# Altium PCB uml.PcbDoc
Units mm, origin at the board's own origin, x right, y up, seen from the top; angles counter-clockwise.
Board outline 71 x 50 mm, 2 copper layers (Top Layer, Bottom Layer); 99 components, 45 nets, 273 pads, 61 vias.
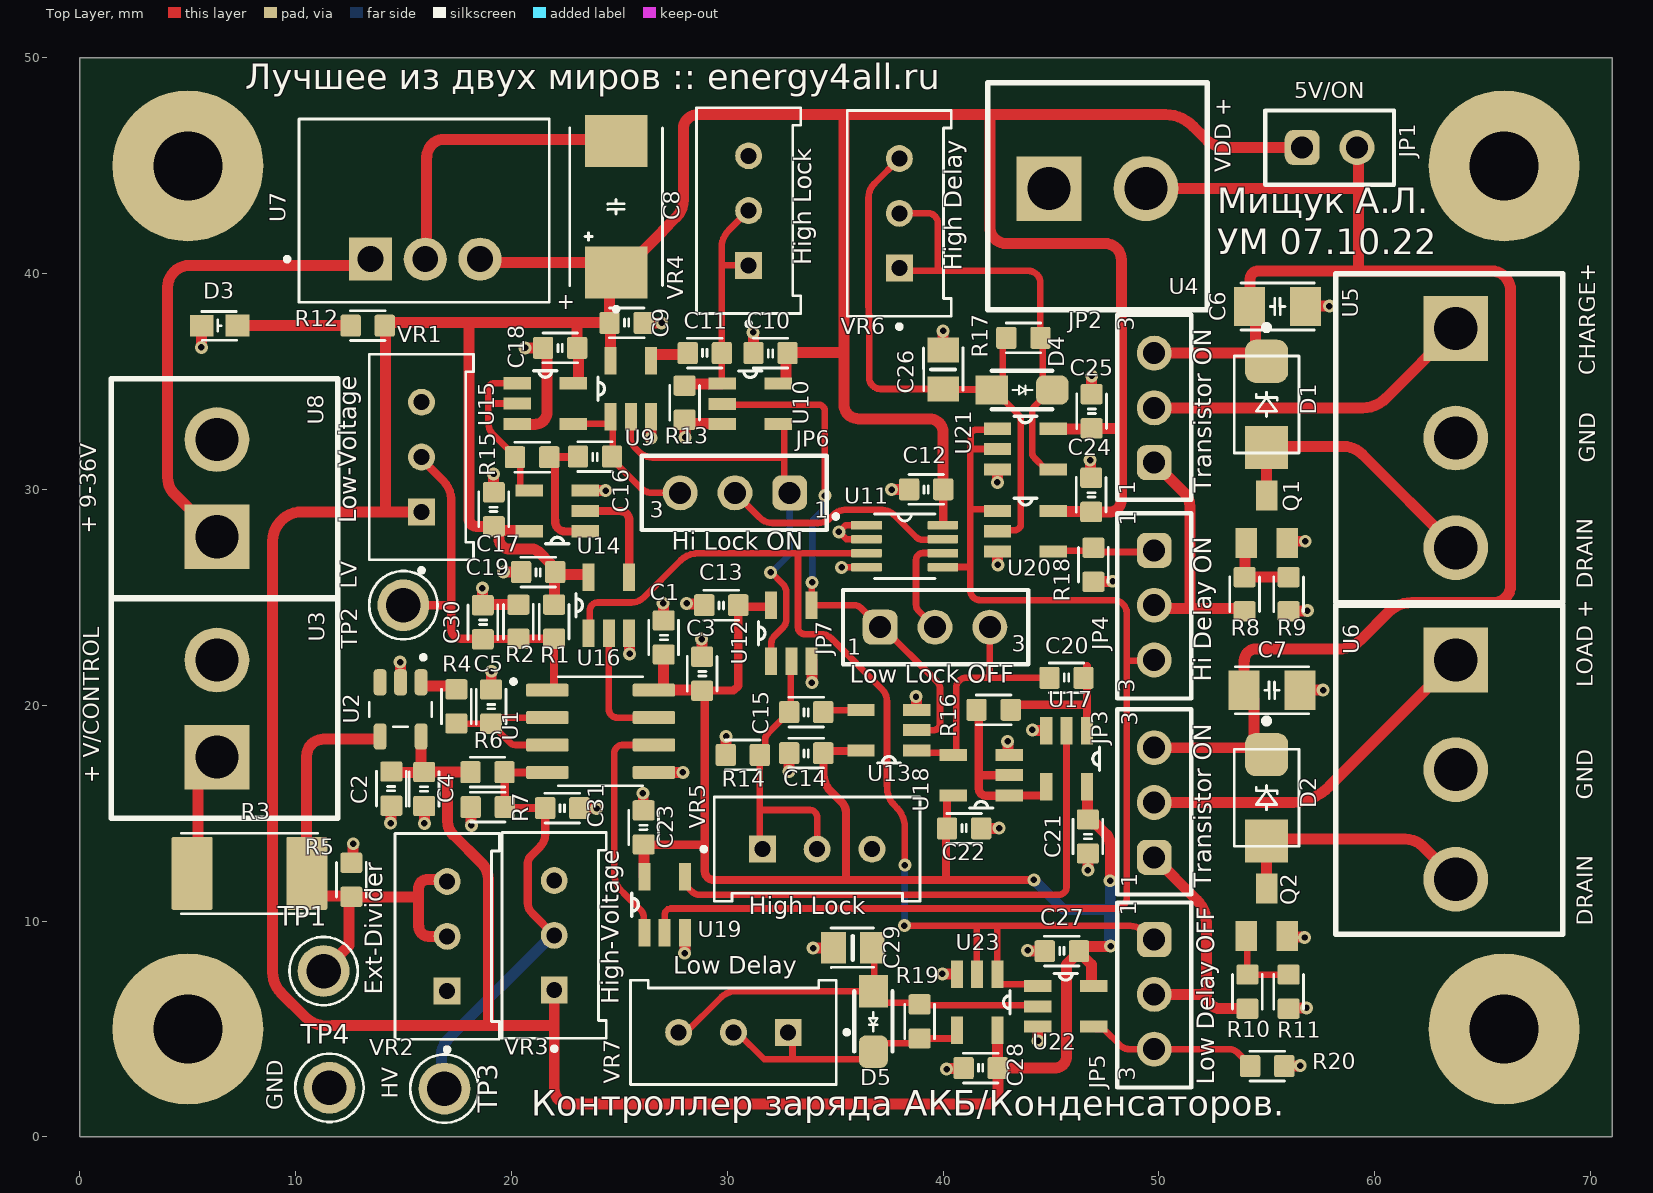
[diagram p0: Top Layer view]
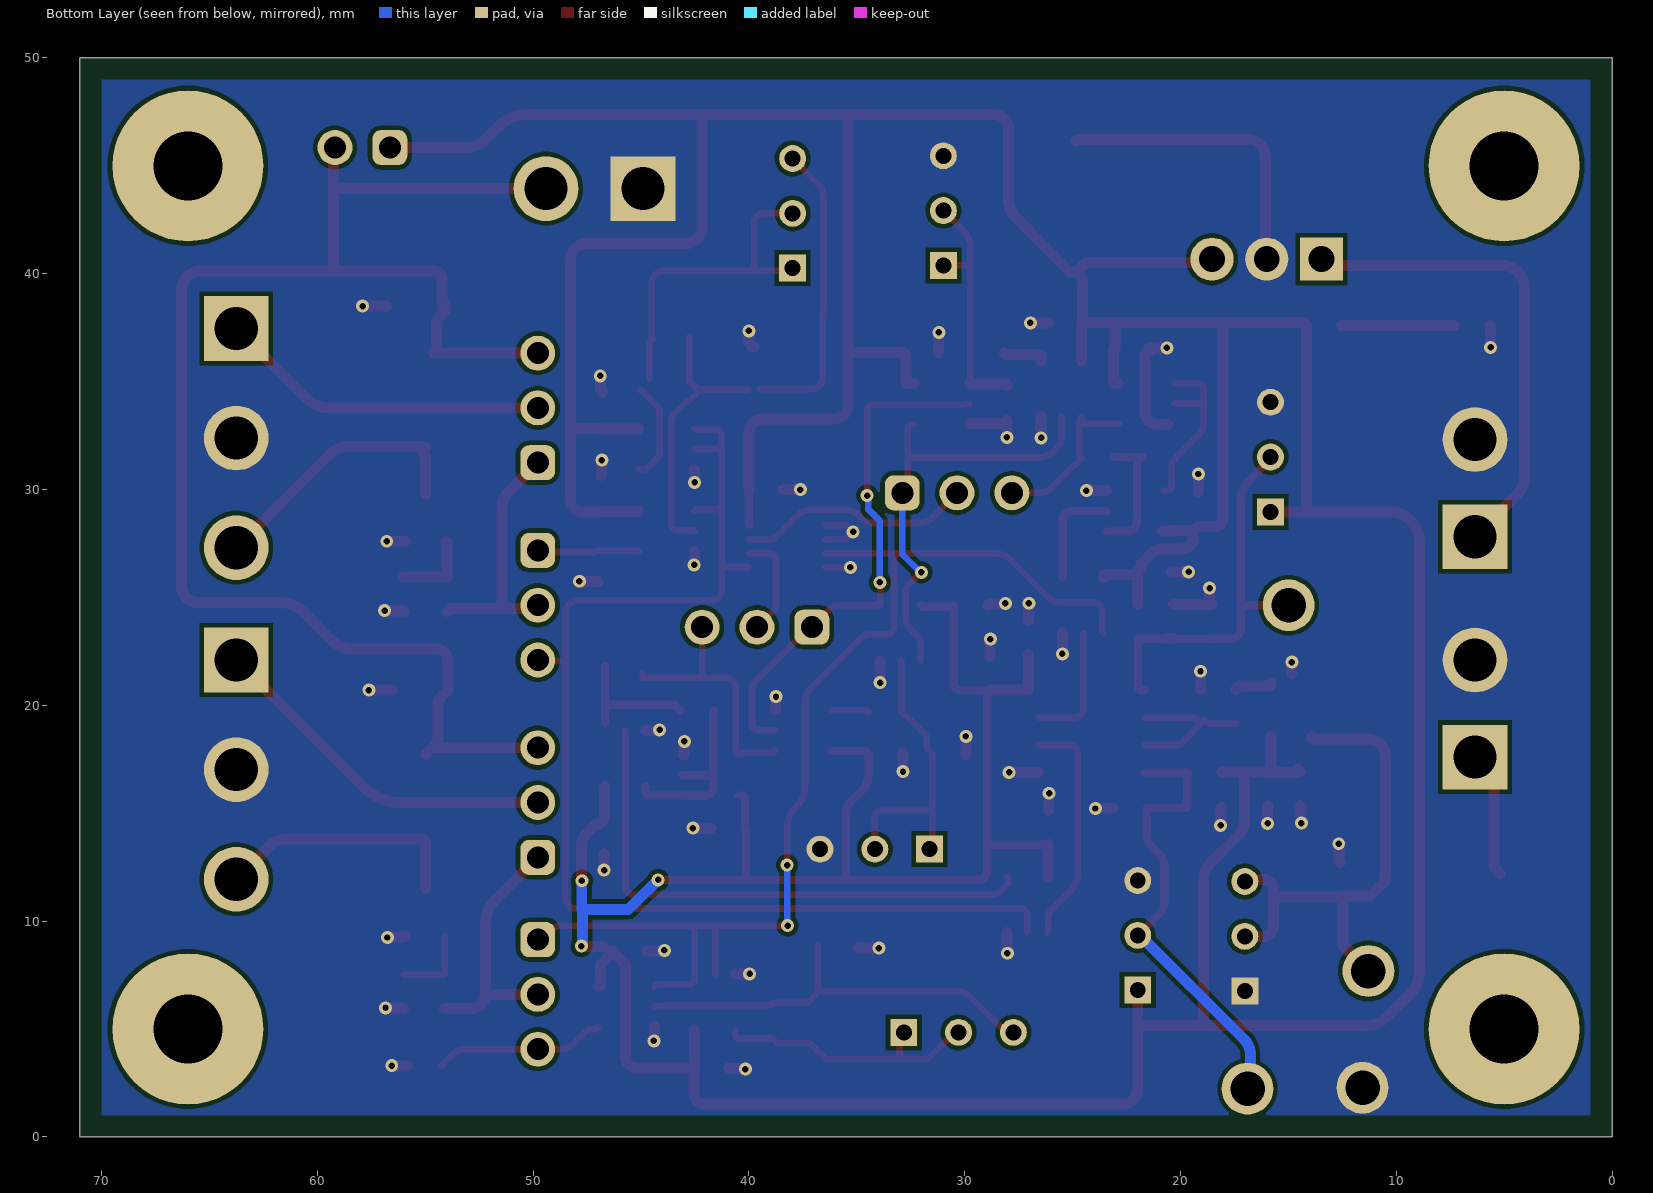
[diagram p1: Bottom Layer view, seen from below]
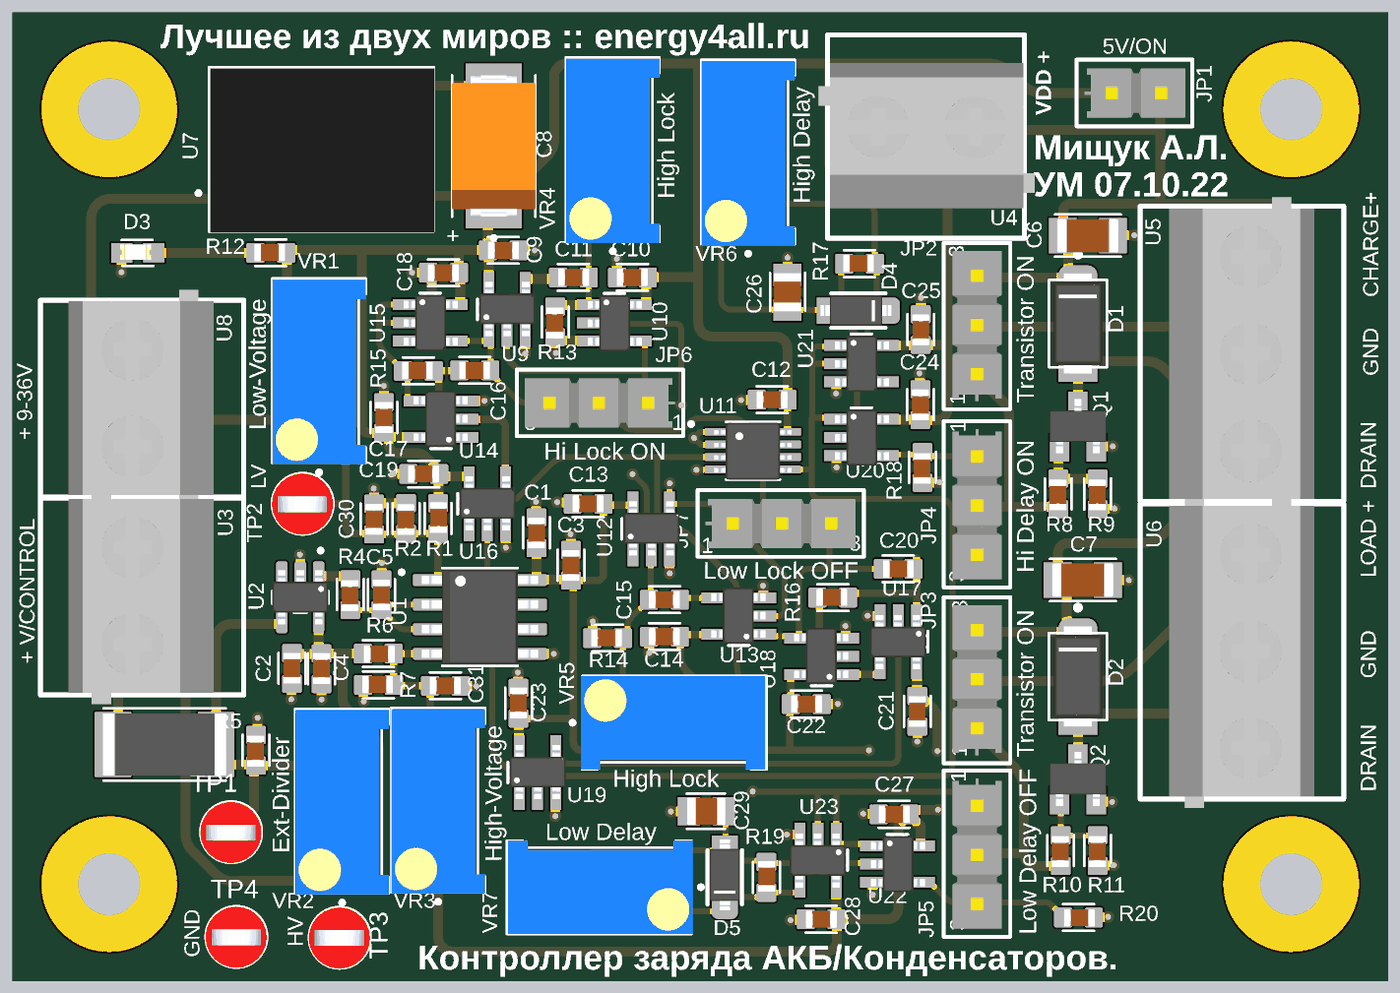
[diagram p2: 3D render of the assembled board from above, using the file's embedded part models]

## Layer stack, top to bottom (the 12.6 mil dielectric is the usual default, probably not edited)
Top Solder: solder mask 0.0102, Solder Resist, Dk 3.5
Top Layer: signal copper 0.0356
Dielectric 1: dielectric 0.32, FR-4, Dk 4.8
Bottom Layer: signal copper 0.0356
Bottom Solder: solder mask 0.0102, Solder Resist, Dk 3.5

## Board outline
0,0 71,0 71,50 0,50

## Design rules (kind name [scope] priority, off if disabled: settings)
Clearance [All] p1: gap=0.2 ignorepadtopadclearanceinfootprint=FALSE except(0: Arc-Hole Track-Hole SMDPad-Hole THPad-Hole Via-Hole Fill-Hole Poly-Hole Region-Hole Text-Hole)
HoleSize [All] p1: absolutevalues=TRUE maxlimit=5.08 minlimit=0.025 maxpercent=80.000 minpercent=20.000
MinimumSolderMaskSliver [All] p1 off: minsoldermaskwidth=0.254
PasteMaskExpansion [All] p1 off: expansion=0
PolygonConnect [All] p1: connectstyle=Direct reliefconductorwidth=0.254 reliefentries=4 polygonreliefangle="90 Angle" airgapwidth=0.254
RoomDefinition lockgen [InComponentClass('lockgen')] p1: confinementstyle=ConfineOut formatcopy=TRUE lockcomponents=FALSE outline 44.755,-5.766 49.301,-5.766 49.301,-2.311 44.755,-2.311
RoomDefinition uDelay [InComponentClass('uDelay')] p2: confinementstyle=ConfineOut formatcopy=TRUE lockcomponents=FALSE outline 50.14,-5.715 54.813,-5.715 54.813,-2.21 50.14,-2.21
RoomDefinition lock [InComponentClass('lock')] p3: confinementstyle=ConfineOut formatcopy=TRUE lockcomponents=FALSE outline 39.497,-5.766 44.12,-5.766 44.12,-2.337 39.497,-2.337
RoomDefinition uSupply [InComponentClass('uSupply')] p4: confinementstyle=ConfineOut formatcopy=TRUE lockcomponents=FALSE outline 33.731,-5.664 38.862,-5.664 38.862,-2.21 33.731,-2.21
RoomDefinition uPower [InComponentClass('uPower')] p5: confinementstyle=ConfineOut formatcopy=TRUE lockcomponents=FALSE outline 27.788,-5.613 32.944,-5.613 32.944,-2.21 27.788,-2.21
RoomDefinition uVoltage [InComponentClass('uVoltage')] p6: confinementstyle=ConfineOut formatcopy=TRUE lockcomponents=FALSE outline 21.895,-5.537 26.899,-5.537 26.899,-2.235 21.895,-2.235
RoutingVias [All] p1: holewidth=0.711 width=1.27 viastyle="Through Hole" minholewidth=0.711 minwidth=1.27 maxholewidth=0.711 maxwidth=1.27
SilkToSilkClearance [All] p1 off: silktosilkclearance=0.127
SilkToSolderMaskClearance [IsPad] p1 off: minsilkscreentomaskgap=0.254 clearancetoexposedcopper=TRUE
SolderMaskExpansion [All] p1 off: expansion=0.102 istentingtop=FALSE
Width [All] p1: maxlimit=1.27 minlimit=0.254 preferedwidth=0.508
25 further rules are at their usual default settings.

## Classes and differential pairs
component class uDelay: C24 C25 C26 C27 C28 C29 D4 D5 JP4 JP5 R17 R18 R19 R20 U20 U21 U22 U23 VR6 VR7
component class lock: C9 C10 C11 C12 C13 C14 C15 JP6 JP7 R13 R14 U9 U10 U11 U12 U13 VR4 VR5
component class lockgen: C16 C17 C18 C19 C20 C21 C22 C23 R15 R16 U14 U15 U16 U17 U18 U19
component class uSupply: C8 D3 R12 U7 U8
component class uPower: C6 C7 D1 D2 JP1 JP2 JP3 Q1 Q2 R8 R9 R10 R11 U4 U5 U6
component class uVoltage: C1 C2 C3 C4 C5 C30 C31 R1 R2 R3 R4 R5 R6 R7 TP1 TP2 TP3 TP4 U1 U2 U3 VR1 VR2 VR3

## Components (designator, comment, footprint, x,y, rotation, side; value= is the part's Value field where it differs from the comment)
C1 "2.2uF" CAP_0603 27.051,23.142 r90 top
C2 "2.2uF" CAP_0603 14.431,16.139 r270 top
C3 "0.1uF" CAP_0603 28.829,21.463 r90 top
C4 "0.1uF" CAP_0603 15.954,16.12 r270 top
C5 "5pF" CAP_0603 19.05,19.939 r90 top
C6 "0.1uF" CAP_1206 55.503,38.481 r180 top
C7 "0.1uF" CAP_1206 55.245,20.701 r180 top
C8 "100uF" CAP_TYPE_D 24.845,43.107 r90 top
C9 "0.1uF" CAP_0603 25.335,37.721 r180 top
C10 "0.1uF" CAP_0603 32.004,36.322 r0 top
C11 "10nF" CAP_0603 28.956,36.322 r180 top
C12 "0.1uF" CAP_0603 39.215,30.01 r0 top
C13 "0.1uF" CAP_0603 29.718,24.638 r0 top
C14 "0.1uF" CAP_0603 33.655,17.78 r0 top
C15 "10nF" CAP_0603 33.655,19.685 r0 top
C16 "10nF" CAP_0603 23.866,31.526 r0 top
C17 "0.1uF" CAP_0603 19.177,29.083 r270 top
C18 "0.1uF" CAP_0603 22.253,36.565 r0 top
C19 "0.1uF" CAP_0603 21.235,26.175 r0 top
C20 "10nF" CAP_0603 45.716,21.274 r180 top
C21 "0.1uF" CAP_0603 46.705,13.923 r90 top
C22 "0.1uF" CAP_0603 40.975,14.295 r180 top
C23 "0.1uF" CAP_0603 26.123,14.341 r270 top
C24 "0.1uF" CAP_0603 46.863,29.754 r90 top
C25 "0.1uF" CAP_0603 46.879,33.628 r90 top
C26 "10nF" CAP_0805 40.005,35.56 r270 top
C27 "0.1uF" CAP_0603 45.503,8.605 r180 top
C28 "0.1uF" CAP_0603 41.741,3.19 r180 top
C29 "10nF" CAP_0805 35.814,8.763 r0 top
C30 "10nF" CAP_0603 18.669,23.848 r90 top
C31 "10nF" CAP_0603 22.352,15.24 r0 top
D1 "MBRA340" MBRA340 54.991,33.691 r270 top
D2 "MBRA340" MBRA340 54.991,15.466 r270 top
D3 "LED/GREEN" LED_0603 6.496,37.592 r0 top
D4 "BAT46WJ" BAT46WJ 43.661,34.611 r0 top
D5 "BAT46WJ" BAT46WJ 36.766,5.351 r270 top
JP1 "5V OR EXT" TSW-102-07-F-S 57.912,45.847 r0 top
JP2 "logical/open drain" TSW-103-07-F-S 49.784,33.782 r90 top
JP3 "logical/open drain" TSW-103-07-F-S 49.784,15.494 r90 top
JP4 "Charge Delay ON/OFF" TSW-103-07-F-S 49.784,24.638 r270 top
JP5 "Load Delay ON/OFF" TSW-103-07-F-S 49.784,6.604 r270 top
JP6 "TSW-103-07-F-S" TSW-103-07-F-S 30.353,29.845 r180 top
JP7 "TSW-103-07-F-S" TSW-103-07-F-S 39.624,23.622 r0 top
Q1 "2N7002" 2N7002 54.991,28.618 r0 top
Q2 "2N7002" 2N7002 54.991,10.414 r0 top
R1 "1K 1%" RESC1608X50N 21.971,23.876 r270 top
R2 "500R 1%" RESC1608X50N 20.32,23.876 r90 top
R3 "499K" RES_2512 7.855,12.21 r0 top
R4 "680 1%" RESC1608X50N 17.442,19.95 r90 top
R5 "DNP" RESC1608X50N 12.575,11.914 r90 top
R6 "500R 1%" RESC1608X50N 18.887,16.9 r180 top
R7 "1K 1%" RESC1608X50N 18.897,15.285 r0 top
R8 "10R" RESC1608X50N 53.975,25.146 r90 top
R9 "10K" RESC1608X50N 56.007,25.146 r90 top
R10 "10R" RESC1608X50N 54.102,6.731 r90 top
R11 "10K" RESC1608X50N 56.007,6.731 r90 top
R12 "10K" RESC1608X50N 13.335,37.592 r0 top
R13 "DNP" RESC1608X50N 28.02,34.024 r90 top
R14 "DNP" RESC1608X50N 30.717,17.701 r0 top
R15 "5K" RESC1608X50N 20.955,31.496 r0 top
R16 "5K" RESC1608X50N 42.341,19.793 r0 top
R17 "DNP" RESC1608X50N 43.721,37.029 r0 top
R18 "100K" RESC1608X50N 46.966,26.512 r90 top
R19 "DNP" RESC1608X50N 38.914,5.351 r270 top
R20 "100K" RESC1608X50N 55.02,3.278 r180 top
TP1 "TP_RED" TP_RED 11.293,7.685 r0 top
TP2 "TP_RED" TP_RED 14.986,24.638 r0 top
TP3 "TP_RED" TP_RED 16.893,2.234 r0 top
TP4 "TP_RED" TP_RED 11.562,2.277 r0 top
U1 "TLV3502AID" TLV3502AID 24.13,18.796 r0 top
U2 "BUF602IDBVT" BUF602IDBVT 14.859,19.812 r270 top
U3 "DG129-5.0-02P" DG129-5.0-02P 6.35,19.848 r90 top
U4 "External Supply" DG129-5.0-02P 47.153,43.942 r0 top
U5 "DG129-5.0-03P" DG129-5.0-03P 63.754,32.385 r270 top
U6 "DG129-5.0-03P" DG129-5.0-03P 63.754,17.018 r270 top
U7 "R-78E5.0-1.0" R-78E5.0-1.0 16.002,42.926 r0 top
U8 "DG129-5.0-02P" DG129-5.0-02P 6.35,30.063 r90 top
U9 "SN74LVC1G00DBVT" SOT23-5 25.527,34.671 r90 top
U10 "SN74LVC1G00DBVT" SOT23-5 31.06,33.972 r0 top
U11 "SN74LVC1G74DCTR" SN74LVC1G74DCTR 38.219,27.376 r0 top
U12 "SN74LVC1G00DBVT" SOT23-5 32.969,23.343 r90 top
U13 "SN74LVC1G00DBVT" SOT23-5 37.49,18.847 r180 top
U14 "SN74LVC1G02DBVT" SOT23-5 22.123,29.007 r180 top
U15 "SN74LVC1G02DBVT" SOT23-5 21.565,33.985 r0 top
U16 "SN74LVC1G00DBVT" SOT23-5 24.511,24.638 r90 top
U17 "SN74LVC1G02DBVT" SOT23-5 45.72,17.526 r270 top
U18 "SN74LVC1G02DBVT" SOT23-5 41.765,16.766 r180 top
U19 "SN74LVC1G00DBVT" SOT23-5 27.098,10.763 r90 top
U20 "SN74LVC1G08DBVT" SOT23-5 43.815,28.067 r0 top
U21 "SN74LVC1G08DBVT" SOT23-5 43.815,31.877 r0 top
U22 "SN74LVC1G08DBVT" SOT23-5 45.68,6.047 r0 top
U23 "SN74LVC1G08DBVT" SOT23-5 41.577,6.245 r270 top
VR1 "5K" TRIM_3296W-1-250 15.829,31.506 r90 top
VR2 "10K" TRIM_3296W-1-250 17.018,9.296 r90 top
VR3 "5K" TRIM_3296W-1-250 21.979,9.339 r90 top
VR4 "5K" TRIM_3296W-1-250 30.988,42.926 r90 top
VR5 "5K" TRIM_3296W-1-250 34.163,13.335 r0 top
VR6 "3296W-1-250" TRIM_3296W-1-250 37.973,42.799 r90 top
VR7 "3296W-1-250" TRIM_3296W-1-250 30.283,4.845 r180 top

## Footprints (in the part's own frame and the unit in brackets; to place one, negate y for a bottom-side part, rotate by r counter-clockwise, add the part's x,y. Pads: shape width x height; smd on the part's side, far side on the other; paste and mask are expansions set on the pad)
2N7002 [mm]
  rect 1x1.4 smd: 1(-0.95,-1.1) 2(0.95,-1.1) 3(0,1.1)
  body extent -1.46,-1.37 1.47,1.43, height 1.24
BAT46WJ [mm]
  rect 1.5x1.35 smd: A(-1.4,0)
  rrect50% 1.5x1.35 smd: C(1.4,0)
  silkscreen extent -1.4,-0.89 1.4,0.89, body extent -1.95,-0.77 1.7,0.78, height 1.45
BUF602IDBVT [mm]
  rrect50% 1.21x0.59 smd: 1(-1.255,0.95) 2(-1.255,0) 3(-1.255,-0.95) 4(1.255,-0.95) 5(1.255,0.95)
  silkscreen extent -2.51,-1.45 0.8,1.45, body extent -1.4,-1.45 1.4,1.45, height 1.45
CAP_0603 [mm]
  rrect20% 0.94x1.02 smd: 1(-0.79,0) 2(0.79,0)
  silkscreen extent -0.8,-0.69 0.8,0.69, body extent -0.81,-0.45 0.79,0.45, height 0.81
CAP_0805 [mm]
  rect 1.15x1.45 smd: 1(-0.9,0) 2(0.9,0)
  silkscreen extent -1.01,-0.91 0.97,0.92, body extent -1,-0.72 1,0.72, height 1.26
CAP_1206 [mm]
  rect 1.44x1.82 smd: 1(-1.295,0) 2(1.295,0)
  silkscreen extent -1.7,-1.09 1.7,1.09, body extent -1.6,-0.89 1.6,0.89, height 1.56
CAP_TYPE_D [mm]
  rect 2.4x2.9 smd: 1(-3.05,0) 2(3.05,0)
  silkscreen extent -4.85,-2.15 3.65,2.15, body extent -3.65,-2.15 3.65,2.15, height 3.1
DG129-5.0-02P [mm]
  rect 3x3 hole 2: 1(-2.25,0)
  round 3 hole 2: 2(2.25,0)
  silkscreen extent -5.08,-5.6 5.08,4.9, body extent -5.55,-4.05 5.61,3.45, height 10.08
DG129-5.0-03P [mm]
  rect 3x3 hole 2: 1(-5.08,0)
  round 3 hole 2: 2(0,0) 3(5.08,0)
  silkscreen extent -7.62,-5.55 7.62,4.95, body extent -8.08,-4.05 8.08,3.45, height 10.08
LED_0603 [mm]
  rect 1.1x1 smd: 1(-0.85,0) 2(0.808,0.009)
  silkscreen extent -0.86,-0.67 0.77,0.66, body extent -0.92,-0.37 0.68,0.43, height 0.55
MBRA340 [mm]
  rect 2x2 smd: A(1.75,0)
  rrect50% 2x2 smd: C(-2.25,0)
  silkscreen extent -3.94,-1.5 2,1.5, body extent -2.86,-1.3 2.35,1.3, height 2.14
R-78E5.0-1.0 [mm]
  rect 2x2 hole 1.2: 1(-2.54,-2.25)
  round 2 hole 1.2: 2(0,-2.25) 3(2.54,-2.25)
  silkscreen extent -6.5,-4.25 5.75,4.25, body extent -5.8,-4.31 5.8,4.19, height 10.41
RES_2512 [mm]
  rrect7% 1.9x3.37 smd: 1(-2.66,0) 2(2.66,0)
  silkscreen extent -3.15,-1.87 3.15,1.87, body extent -3.17,-1.6 3.18,1.6, height 0.65
RESC1608X50N [mm]
  rrect20% 0.94x1.02 smd: 1(-0.79,0) 2(0.79,0)
  silkscreen extent -0.8,-0.69 0.8,0.69, body extent -0.85,-0.43 0.75,0.47, height 0.79
SN74LVC1G74DCTR [mm]
  rect 1.42x0.4 smd: 1(-1.77,0.975)
  rrect25% 1.42x0.4 smd: 2(-1.77,0.325) 3(-1.77,-0.325) 4(-1.77,-0.975) 5(1.77,-0.975) 6(1.77,-0.325) 7(1.77,0.325) 8(1.77,0.975)
  silkscreen extent -3.29,-1.5 1.4,1.5, body extent -2,-1.5 2,1.45, height 1.3
SOT23-5 [mil]
  rect 50x22 smd: 1(-51,37) 2(-51,0) 3(-51,-37) 4(51,-37) 5(51,37)
  silkscreen extent -21,48 21,60, body extent -54,-58 56,56, height 57
TLV3502AID [mm]
  rrect25% 1.97x0.6 smd: 1(-2.47,1.905) 2(-2.47,0.635) 3(-2.47,-0.635) 4(-2.47,-1.905) 5(2.47,-1.905) 6(2.47,-0.635) 7(2.47,0.635) 8(2.47,1.905)
  silkscreen extent -4.14,-2.52 1.95,2.52, body extent -3,-2.45 3,2.45, height 1.75
TP_RED [mm]
  round 2.4 hole 1.6: 1(0,0)
  silkscreen extent -1.59,-1.58 1.59,1.58, body extent -1.6,-1.61 1.57,1.57, height 8.13
TRIM_3296W-1-250 [mm]
  rect 1.248x1.248 hole 0.74: 1(-2.54,0)
  round 1.248 hole 0.74: 2(0,0) 3(2.54,0)
  silkscreen extent -5.35,-2.41 4.76,2.42, body extent -4.83,-2.42 4.7,2.42, height 11.55
TSW-102-07-F-S [mm]
  rrect50% 1.62x1.62 hole 1.02: 1(-1.27,0)
  round 1.62 hole 1.02: 2(1.27,0)
  silkscreen extent -2.99,-1.72 2.98,1.72, body extent -2.58,-1.28 2.62,1.26, height 8.38
TSW-103-07-F-S [mm]
  rrect50% 1.62x1.62 hole 1.02: 1(-2.54,0)
  round 1.62 hole 1.02: 2(0,0) 3(2.54,0)
  silkscreen extent -4.26,-1.72 4.32,1.72, body extent -3.85,-1.27 3.9,1.27, height 8.38

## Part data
C1 C2 C3 C4 C5 C9 C10 C11 C12 C13 C14 C15 C16 C17 C18 C19 C20 C21 C22 C23 C24 C25 C27 C28 C30 C31: library part CAP_0603
C6 C7: library part CAP_1206
C8: library part CAP_TYPE_D, Package=None
C26 C29: library part CAP_0805
D1 D2: "DIODE, SCHOTTKY, 3A, 40V, SMA", Package="DO-214 ON Semiconductor"
D3: library part LED_0603, "Blue 470nm LED Indication - Discrete 3.3V 0603 _1608 Metric_", Package="0603 Lite-On"
D4 D5: "Diode Schottky 100V 250mA (DC) Surface Mount SOD-323F", Package="SOD-323 NXP Semiconductors"
JP1: library part TSW-102-07-F-S
JP2 JP3 JP4 JP5: library part TSW-103-07-F-S
Q1 Q2: "N-Channel 60V 200mA _Tc_ 350mW _Tc_ Surface Mount SOT-23-3", Package="SOT-23-3 Vishay"
R1 R2 R4 R5 R6 R7 R8 R9 R10 R11 R12 R13 R14 R15 R16 R17 R18 R19 R20: library part RES_0603, "1% 0.1W", Package=None
R3: library part RES_2512, "2512 1% 1W", Package=None
TP1 TP2 TP3 TP4: "RF EMI Absorbing Sheet - Polyurethane Foam 24.000 (609.60mm) X 24.000 (609.60mm) X 0.252 (6.40mm)", Package="TO-66 Aeroflex"
U1: "4.5ns Rail-to-Rail Comparator", Package="SOIC-8 Texas Instruments"
U2: "1000MHz,Wide Bandwidth, High-Speed, Closed Loop Buffer 5-SOT-23 -45 to 85", Package="SOT-23-5 Texas Instruments"
U3 U8: "DG129-5.0-02P-14-00A(H)"
U4: library part DG129-5.0-02P, "DG129-5.0-02P-14-00A(H)"
U5 U6: "DG129-5.0-03P-14-00AH"
U7: "1A DC/DC-Converter SIP3", Package="SIP-3 Recom Power"
U9 U10 U12 U13 U16 U19: "NAND IC 1 canal SOT-23-5", Package="SOT-23 Texas Instruments"
U11: "Single Positive-Edge-Triggered D-Type Flip-Flop With Clear and Preset 8-SM8 -40 to 125", Package="SSOP-8 Texas Instruments"
U14 U15 U17 U18: "NOR IC 1 canal SOT-23-5", Package="SOT-23 Texas Instruments"
U20 U21 U22 U23: "AND IC 1 chanal SOT-23-5", Package="SOT-23 Texas Instruments"
VR1 VR2 VR3 VR4 VR5: library part 3296W-1-250, "25 Ohms 0.5W, 1/2W PC Pins Through Hole Trimmer Potentiometer Cermet 25 Turn Top Adjustment", Package="SOT-23-5 Bourns"
VR6 VR7: "25 Ohms 0.5W, 1/2W PC Pins Through Hole Trimmer Potentiometer Cermet 25 Turn Top Adjustment", Package="SOT-23-5 Bourns"

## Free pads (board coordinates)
  round 7 hole 3.2: 1(5,5) 2(5,45) 3(66,45) 4(66,5)

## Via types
v1: diameter 0.6, hole 0.3, Top Layer to Bottom Layer, tented both sides, 61 vias

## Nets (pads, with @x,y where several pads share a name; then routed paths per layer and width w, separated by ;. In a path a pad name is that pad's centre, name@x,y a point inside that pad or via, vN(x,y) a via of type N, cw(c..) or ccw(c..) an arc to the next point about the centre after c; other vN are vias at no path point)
+5V: C1.1 C2.1 C3.1 C4.1 C8.1 C9.2 C10.2 C12.2 C13.2 C14.2 C17.2 C18.2 C19.2 C21.2 C22.2 C23.2 C24.1 C25.1 C27.1 C28.1 JP1.1 R1.1 R6.2 R12.2 U1.8 U2.5 U7.3 U9.5 U10.5 U11.8 U12.5 U13.5 U14.5 U15.5 U16.5 U17.5 U18.5 U19.5 U20.5 U21.5 U22.5 U23.5 VR1.1 VR3.1 | length 308.6
  Top Layer w0.381: C23.2@26.211,13.515 26.232,13.536 28.956,13.536 ; C3.1 28.956,20.546 28.956,13.536 ; C3.1@28.838,20.682 30.285,20.682 30.508,20.905 C13.2@30.508,24.567 ; 29.365,11.907 35.494,11.907 ; 29.365,11.912 cw(c29.365,12.321) 28.956,12.321 28.956,13.536 ; C13.2 C13.2@30.508,24.567 ; U12.5 32.011,24.638 31.941,24.567 C13.2@30.508,24.567 ; C14.2@34.452,17.733 C14.2@34.462,17.743 ; C14.2@34.462,17.763 C14.2@34.462,17.743 ; 34.783,16.025 34.779,16.029 cw(c35.546,16.796) 34.705,16.112 cw(c35.546,16.796) 34.462,16.796 C14.2@34.462,17.743 ; 34.787,16.029 35.298,15.519 cw(c34.826,15.046) 35.494,15.046 35.494,11.907 ; U13.5@36.171,17.883 34.602,17.883 C14.2@34.462,17.743 ; U11.8 39.996,28.351 40.005,28.36 C12.2@40.005,29.972 ; U18.5 40.273,15.826 40.185,15.737 C22.2 40.132,14.243 40.132,11.907 ; v1(44.206,11.909) 44.204,11.907 40.132,11.907 ; 35.494,11.907 40.132,11.907
  Top Layer w0.508: 14.163,29.21 14.163,37.554 R12.2 14.272,37.739 18.034,37.739 ; C2.1 C2.1@14.562,17.06 ; C2.1@14.587,16.906 14.61,16.882 15.884,16.882 C4.1@15.937,16.936 ; C4.1@15.802,17.081 U2.5@15.802,18.55 ; VR1.1 10.289,28.966 ccw(c10.289,27.609) 8.932,27.609 8.932,7.619 8.932,7.617 ccw(c10.261,7.617) 9.323,6.675 10.43,5.568 ccw(c11.455,6.59) 11.705,5.165 cw(c11.793,4.664) 11.793,5.172 18.923,5.172 ; C4.1@15.964,16.918 17.037,16.918 ; R6.2 18.08,16.918 17.037,16.918 ; 18.375,28.293 C17.2 19.196,28.293 C17.2@19.397,28.092 ; 18.375,28.295 cw(c18.375,28.636) 18.034,28.636 18.034,37.739 ; U7.3 18.693,40.525 24.377,40.525 C8.1 ; 19.412,27.741 ccw(c19.91,27.741) 19.514,27.439 ccw(c19.91,27.741) 19.608,27.346 ccw(c19.91,27.741) 19.91,27.244 20.928,27.244 cw(c20.928,26.757) 21.235,27.135 cw(c20.928,26.757) 21.273,27.101 ; C17.2@19.412,28.092 20.447,28.092 20.472,28.067 U14.5 ; 21.271,27.1 21.809,26.562 21.809,26.391 C19.2 ; R1.1 21.998,24.693 21.998,26.148 C19.2 ; VR3.1 21.979,5.172 ; U15.5 23.087,34.925 23.112,34.95 C18.2@23.112,36.496 ; C18.2 23.03,36.578 23.03,37.739 ; U16.5 23.571,26.029 23.546,26.054 22.145,26.054 C19.2 ; U9.5 24.588,37.678 C9.2 ; C23.2@26.127,13.548 26.141,13.533 26.141,12.076 U19.5 ; U1.8@27.051,20.711 28.791,20.711 C3.1 ; U1.8@27.051,20.747 C1.1 ; 27.969,46.701 27.969,43.434 cw(c26.811,43.434) 27.63,42.616 27.002,41.988 27.002,41.964 25.095,40.057 C8.1 ; 27.969,46.821 cw(c28.627,46.701) 28.627,47.371 35.398,47.371 ; U10.5 32.683,34.912 32.709,34.937 C10.2@32.709,36.237 ; C10.2@32.813,36.341 35.398,36.341 ; C12.2@40.005,29.972 40.005,32.639 ccw(c39.37,32.639) 39.37,33.274 36.083,33.274 cw(c36.083,33.959) 35.398,33.959 35.398,36.341 ; C28.1@42.524,3.197 U23.5@42.524,4.943 ; 42.545,2.032 cw(c42.037,2.032) 42.037,1.524 22.679,1.524 cw(c22.679,2.224) 21.979,2.224 21.979,5.172 ; 42.554,2.032 C28.1@42.554,3.167 ; C28.1@42.554,3.189 45.167,3.189 ; U20.5 45.12,29.016 45.151,28.985 46.842,28.985 C24.1 47.119,28.956 47.698,28.956 ccw(c47.698,29.518) 48.26,29.518 48.26,32.826 ; U21.5 45.115,32.812 C25.1@46.854,32.812 ; 45.232,3.189 ccw(c45.167,3.738) 45.72,3.738 45.72,7.993 C27.1@46.293,8.565 ; C27.1 C27.1@46.293,8.565 ; U17.5@46.662,16.228 46.682,16.208 46.682,14.736 C21.2 46.921,14.497 47.08,14.497 47.531,14.046 cw(c47.001,13.516) 47.751,13.516 ; C27.1@46.732,8.822 47.748,8.822 v1(47.766,8.839) ; C25.1@46.868,32.826 48.26,32.826 ; U22.5 46.905,6.986 46.88,7.012 46.88,7.994 46.864,7.994 C27.1@46.293,8.565 ; v1(47.74,11.871) 47.753,11.884 47.753,13.516 ; 52.129,46.284 51.593,46.82 51.591,46.822 cw(c51.952,47.179) 51.587,46.826 ccw(c50.313,45.611) 50.313,47.371 50.311,47.371 42.164,47.371 ; 52.258,46.155 ccw(c53.156,47.311) 53.156,45.847 JP1.1 ; 17.037,16.918 17.037,14.618 ccw(c17.899,14.618) 17.298,14 18.633,12.664 cw(c17.934,11.965) 18.923,11.965 18.923,5.172 ; 18.034,37.739 23.03,37.739 ; 18.923,5.172 21.979,5.172 ; 23.03,37.739 24.527,37.739 C9.2 ; C9.2 24.545,39.758 C8.1 ; 35.398,36.341 35.398,47.371 ; 35.398,47.371 42.164,47.371 ; 42.164,47.371 42.164,42.168 ccw(c42.93,42.168) 42.93,41.402 47.503,41.402 cw(c47.503,40.645) 48.26,40.645 48.26,32.826
  Bottom Layer w0.508: v1(44.206,11.909) 44.694,11.42 ; 44.704,11.43 45.593,10.541 47.745,10.541 v1@47.745,11.866 ; 47.715,10.541 47.715,8.915 47.766,8.864 v1(47.766,8.839)
+12V: C6.2 C7.2 D1.C D2.C JP1.2 JP2.3 JP3.3 U4.2 | length 74.4
  Top Layer w0.508: U4.2@49.403,42.926 U4.2@50.038,43.561 ; U4.2 59.182,43.942 ; JP3.3 D2.C@54.673,18.034 ; JP2.3 D1.C@54.61,36.322 ; 53.95,22.079 C7.2 54.416,20.235 54.416,18.291 D2.C@54.673,18.034 ; 53.957,22.079 cw(c54.484,22.079) 54.484,22.606 58.293,22.606 ccw(c58.293,24.136) 59.375,23.054 ; C6.2@54.052,38.291 54.483,37.86 D1.C@54.483,36.449 ; C6.2@54.092,38.598 C6.2 ; C6.2@54.229,38.735 54.229,39.751 cw(c54.61,39.751) 54.61,40.132 59.242,40.132 ; D2.C D2.C@54.673,18.034 ; JP1.2 59.242,45.787 59.242,40.132 ; 59.399,23.077 60.638,24.316 cw(c61.722,23.232) 61.722,24.765 65.532,24.765 ccw(c65.532,25.527) 66.294,25.527 66.294,39.243 ccw(c65.405,39.243) 65.405,40.132 59.242,40.132
GND: C1.2 C2.2 C3.2 C4.2 C5.2 C6.1 C7.1 C8.2 C9.1 C10.1 C12.1 C13.1 C14.1 C17.1 C18.1 C19.1 C21.1 C22.1 C23.1 C24.2 C25.2 C26.1 C27.2 C28.2 C29.1 C30.2 C31.2 D3.1 Q1.2 Q2.2 R2.2 R5.2 R7.1 R9.1 R11.1 R13.1 R14.1 R18.1 R20.1 TP4.1 U1.5 U2.2 U3.2 U4.1 U5.2 U6.2 U7.2 U8.2 U9.3 U10.3 U11.1 U11.2 U11.4 U12.3 U13.3 U14.3 U15.3 U16.3 U17.3 U18.3 U19.3 U20.3 U21.3 U22.3 U23.3 VR1.3 VR2.1 VR3.3 VR4.3 VR5.3 | length 69
  Top Layer w0.305: v1(35.297,26.391) 35.302,26.396 36.444,26.396 U11.4 ; U11.2@36.433,27.685 36.425,27.692 35.523,27.692 v1(35.175,28.04) 35.487,28.352 36.434,28.352 U11.1@36.441,28.359
  Top Layer w0.508: v1(5.629,36.591) 5.638,36.599 5.638,37.584 D3.1 ; R5.2 12.648,12.777 12.648,13.568 v1(12.666,13.585) ; v1(14.397,14.543) 14.414,14.559 14.414,15.332 C2.2 ; v1(14.841,22.006) 14.859,21.989 U2.2@14.859,21.463 ; C4.2 15.957,15.327 15.957,14.529 v1(15.959,14.526) ; U7.2 16.066,40.74 16.066,45.438 ; 16.084,45.438 cw(c16.876,45.438) 16.876,46.23 24.772,46.23 C8.2 ; R7.1 18.123,15.269 18.123,14.449 v1(18.139,14.433) ; C30.2@18.544,24.666 R2.2 ; v1(18.649,25.435) 18.659,25.425 18.659,24.648 C30.2 ; C5.2 19.061,20.74 19.061,21.566 v1(19.072,21.578) ; v1(19.17,30.72) 19.173,30.717 19.173,29.877 C17.1 ; v1(19.625,26.181) 19.628,26.178 20.441,26.178 C19.1 ; U15.3@20.574,33.02 21.082,33.02 ccw(c21.082,33.58) 21.642,33.58 21.642,33.633 21.642,36.202 C18.1@21.371,36.473 ; v1(20.629,36.567) v1(20.629,36.567) 21.462,36.566 C18.1 ; C18.1@21.462,36.526 C18.1 ; C18.1 C18.1 ; C31.2 23.153,15.229 23.933,15.229 v1(23.944,15.218) ; U14.3 23.421,29.948 v1(24.362,29.95) v1(24.362,29.95) ; U16.3 25.461,23.332 25.461,22.39 v1(25.472,22.379) ; v1(26.088,15.925) 26.105,15.907 26.105,15.149 C23.1 ; C9.1 v1(26.958,37.721) ; v1(26.46,32.39) 26.463,32.394 26.463,33.372 U9.3 ; U1.5 v1(27.94,16.891) ; v1(27.027,24.73) 27.039,24.718 27.039,23.944 C1.2 ; v1(28.02,8.511) 28.029,8.52 28.029,9.459 U19.3 ; v1(28.041,32.421) 28.03,32.431 28.03,33.158 R13.1@28.074,33.201 ; R13.1@28.046,33.173 28.161,33.058 29.739,33.058 U10.3 ; v1(28.115,24.72) 28.133,24.703 28.863,24.703 C13.1 ; v1(28.81,23.064) 28.82,23.054 28.82,22.262 C3.2 ; R14.1 29.938,17.712 29.938,18.553 v1(29.949,18.564) ; v1(31.192,37.28) 31.203,37.269 31.203,36.333 C10.1 ; v1(32.858,16.929) 32.862,16.932 32.862,17.777 C14.1 ; U12.3 33.915,22.041 33.915,21.054 v1(33.921,21.048) ; v1(33.98,8.749) 33.988,8.756 34.891,8.756 C29.1@34.914,8.779 ; v1(37.613,29.991) 37.623,30.001 38.416,30.001 C12.1 ; v1(38.744,20.405) 38.761,20.387 38.761,19.811 U13.3 ; C26.1@39.751,36.601 39.825,36.601 40.005,36.781 v1(40.005,37.348) ; v1(39.969,7.557) 39.977,7.549 40.629,7.549 U23.3 ; v1(40.16,3.144) 40.178,3.161 40.922,3.161 C28.2 ; C22.1 41.77,14.3 42.589,14.3 v1(42.594,14.305) ; v1(42.51,30.331) 42.515,30.336 42.515,30.933 U21.3 ; U20.3 42.527,27.12 42.527,26.52 v1(42.534,26.512) ; v1(42.993,18.324) 43.01,18.307 43.01,17.731 43.036,17.706 U18.3 ; v1(43.913,8.639) 43.929,8.622 44.696,8.622 C27.2 ; v1(44.134,18.858) 44.152,18.841 44.761,18.841 U17.3 ; U22.3 44.395,5.096 44.395,4.463 v1(44.405,4.453) ; C21.1 46.706,13.132 46.706,12.359 v1(46.707,12.358) ; C25.2@46.78,34.527 46.884,34.631 46.884,35.266 v1(46.888,35.27) ; v1(46.813,31.366) 46.83,31.348 46.83,30.676 C24.2@46.863,30.643 ; R18.1 46.98,25.736 47.841,25.736 v1(47.855,25.75) ; R20.1 55.823,3.291 56.538,3.291 v1(56.551,3.305) ; Q2.2 55.997,9.258 56.738,9.258 v1(56.756,9.24) ; Q1.2@55.941,27.602 v1(56.783,27.602) ; R11.1 56.029,5.963 56.823,5.963 v1(56.84,5.981) ; R9.1 56.023,24.372 56.861,24.372 v1(56.878,24.389) ; C7.1 56.542,20.699 v1(57.611,20.699) ; C6.1 56.813,38.497 v1(57.899,38.497)
NetC5_1: C5.1 R4.1 U1.2 U1.3 | length 7.5
  Top Layer w0.305: R4.1 17.448,19.155 18.692,19.155 18.697,19.15 18.697,19.146 18.875,19.324 C5.1 ; U1.3 20.193,18.161 cw(c20.193,18.535) 19.928,18.271 19.408,18.791 19.408,18.831 19.09,19.149 C5.1 ; U1.2 19.332,19.431 C5.1
NetC11_1: C11.1 R13.2 U10.1 VR4.1 VR4.2 | length 11.5
  Top Layer w0.305: 29.739,41.221 cw(c30.839,41.221) 29.746,41.347 cw(c30.839,41.221) 30.061,41.999 VR4.2 ; U10.1@29.745,34.892 U10.1 29.746,34.93 C11.1 29.746,40.386 ; 29.746,41.221 29.746,40.386 ; VR4.1 29.746,40.386
  Top Layer w0.508: R13.2 28.092,34.886 29.739,34.886 U10.1
NetC11_2: C11.2 U9.4 | length 2
  Top Layer w0.508: U9.4 26.467,36.223 26.492,36.248 28.092,36.248 C11.2
NetC15_1: C15.1 R14.2 U12.2 VR5.1 VR5.2 | length 13.9
  Top Layer w0.305: R14.2@31.483,17.739 31.753,18.009 31.753,18.415 cw(c32.103,18.415) 31.855,18.663 31.914,18.722 ; VR5.1@31.496,13.208 ccw(c31.468,13.236) 31.507,13.236 31.507,15.147 ; R14.2 31.507,15.147 ; 31.908,18.728 32.507,19.327 32.547,19.327 C15.1@32.945,19.725 ; C15.1 32.905,19.685 C15.1@32.945,19.725 ; U12.2 32.969,22.069 32.945,22.094 C15.1@32.945,19.725 ; VR5.2 34.163,14.811 ccw(c33.827,14.811) 33.827,15.147 31.507,15.147
NetC15_2: C15.2 U13.4 | length 1.8
  Top Layer w0.305: C15.2 34.53,19.77 U13.4@36.179,19.77
NetC16_1: C16.1 R15.2 U14.1 | length 6.1
  Top Layer w0.381: R15.2 22.012,31.229 22.012,28.563 ; R15.2@21.745,31.499 21.757,31.511 23.061,31.511 C16.1 ; 22.023,28.563 22.023,28.514 ccw(c22.479,28.514) 22.479,28.058 U14.1@23.409,28.058
NetC16_2: C16.2 JP6.3 U9.1 U15.4 | length 7.5
  Top Layer w0.305: U15.4 U9.1@24.587,33.045 ; U9.1@24.587,33.212 24.627,33.172 24.627,33.336 U9.1 ; C16.2 24.573,31.442 24.847,31.168 24.887,31.168 25.974,30.08 ccw(c26.543,30.649) 26.543,29.845 JP6.3 ; C16.2@24.69,31.599 U9.1@24.69,33.109
NetC20_1: C20.1 R16.2 U17.1 | length 6.3
  Top Layer w0.381: R16.2@43.172,19.745 43.451,20.024 46.666,20.024 ; 46.666,19.677 46.666,20.024 ; 46.666,21.826 46.666,21.274 46.666,20.024 ; U17.1@46.673,19.169 46.673,19.677
NetC20_2: C20.2 JP7.3 U13.1 U18.4 | length 11.8
  Top Layer w0.305: U13.1 38.886,17.806 40.209,17.806 U18.4@40.31,17.706 ; U18.4@40.361,17.815 U18.4 40.478,17.706 40.605,17.833 40.605,20.811 cw(c41.068,20.811) 41.068,21.274 42.164,21.274 C20.2 ; 42.164,21.377 JP7.3 ; C20.2@44.926,21.463 C20.2@44.93,21.463
NetC26_2: C26.2 D4.A R17.1 U20.2 VR6.3 | length 26.9
  Top Layer w0.305: 36.576,35.181 ccw(c37.097,35.181) 37.112,34.66 37.115,34.66 39.432,34.66 C26.2@39.497,34.66 ; 36.576,35.183 36.576,37.972 ccw(c36.485,37.972) 36.567,38.011 cw(c42.162,38.547) 36.542,38.549 36.542,43.5 cw(c37.526,43.5) 36.83,44.196 VR6.3 ; C26.2 40.031,34.634 42.238,34.634 42.295,34.577 42.784,34.088 42.872,34.088 43.462,33.499 cw(c43.119,33.156) 43.602,33.2 cw(c43.119,33.156) 43.604,33.156 ; D4.A@42.329,34.611 42.771,35.052 R17.1@42.771,37.084 ; U20.2 42.567,28.115 43.309,28.115 ccw(c43.309,28.409) 43.598,28.357 ccw(c43.309,28.409) 43.603,28.409 ; 43.602,28.456 43.602,33.156
NetC29_2: C29.2 D5.A R19.1 U22.2 VR7.3 | length 19.9
  Top Layer w0.305: VR7.3 27.761,4.826 27.94,4.826 28.065,4.826 29.691,6.452 ; 29.697,6.446 29.726,6.475 cw(c30.393,5.808) 30.393,6.751 D5.A ; C29.2@36.819,8.89 36.801,8.872 36.801,8.687 36.801,6.786 D5.A ; R19.1@38.902,6.154 38.959,6.096 43.902,6.096 43.951,6.047 U22.2 ; R19.1 38.838,6.217 37.289,6.217 36.766,6.739 D5.A
NetC30_1: C30.1 R1.2 R2.1 TP2.1 U1.1 VR1.2 | length 18.4
  Top Layer w0.381: TP2.1 17.203,24.638 ; VR1.2 15.829,31.415 16.826,30.418 cw(c15.895,29.488) 17.206,29.369 ; 17.203,29.369 17.203,24.638 ; 17.682,23.086 18.641,23.086 C30.1 18.683,23.072 20.306,23.072 R2.1 ; 17.682,23.089 17.663,23.089 cw(c17.663,23.549) 17.203,23.549 17.203,24.638 ; R2.1@20.616,23.109 20.64,23.086 R1.2 21.971,20.81 21.862,20.701 U1.1
  Top Layer w0.508: R2.1 R2.1@20.616,23.086
NetC31_1: C31.1 R6.1 R7.2 TP3.1 U1.4 VR3.2 | length 21.7
  Top Layer w0.381: TP3.1 TP3.1@17.02,2.361 ; R7.2 19.682,15.28 R7.2@19.682,15.274 ; 20.942,10.376 VR3.2 ; 20.946,10.38 cw(c21.407,10.841) 20.755,10.841 20.755,12.636 20.753,12.638 cw(c21.335,12.638) 20.755,12.687 cw(c21.335,12.638) 20.923,13.049 21.336,13.462 ccw(c20.79,14.008) 21.562,14.008 C31.1 19.716,15.24 R7.2@19.682,15.274 ; U1.4 19.677,16.891 R6.1 19.682,16.896 R7.2@19.682,15.274
  Bottom Layer w0.508: TP3.1 16.764,2.363 16.764,3.841 cw(c17.698,3.841) 17.038,4.501 ; 17.037,4.502 21.875,9.339 VR3.2
NetD1_A: D1.A Q1.3 U5.3 | length 13
  Top Layer w0.508: Q1.3@54.991,29.802 54.991,31.559 55.182,31.75 D1.A 55.047,31.997 55.182,31.997 58.547,31.997 cw(c58.547,30.754) 59.426,31.633 U5.3
NetD2_A: D2.A Q2.3 U6.3 | length 11.7
  Top Layer w0.508: Q2.3 D2.A 55.078,13.803 61.406,13.803 cw(c61.406,12.638) 62.228,13.464 cw(c61.406,12.638) 62.23,13.462 U6.3
NetD3_2: D3.2 R12.1 | length 5.2
  Top Layer w0.508: D3.2 7.313,37.592 R12.1
NetD4_C: D4.C R17.2 U21.4 VR6.1 VR6.2 | length 20.4
  Top Layer w0.305: VR6.1 38.1,40.132 39.751,40.132 ; VR6.2@37.978,42.804 39.302,42.804 cw(c39.302,42.356) 39.751,42.364 cw(c39.302,42.356) 39.751,42.356 39.751,40.132 ; 44.123,33.435 44.123,31.724 ccw(c44.491,31.724) 44.231,31.465 ; 44.125,33.435 44.125,33.581 cw(c44.524,33.581) 44.242,33.863 44.99,34.611 D4.C ; 44.229,31.463 44.755,30.937 U21.4 ; D4.C@44.618,35.119 44.618,36.817 44.453,36.982 44.506,37.034 44.506,39.584 ccw(c43.958,39.584) 43.958,40.132 39.751,40.132
NetD5_C: D5.C R19.2 U23.4 VR7.1 VR7.2 | length 12.9
  Top Layer w0.305: VR7.2 30.461,4.845 31.708,3.598 31.989,3.598 ccw(c32.067,4.454) 32.067,3.594 32.133,3.594 ; 32.133,3.598 33.02,3.598 ; VR7.1 33.02,4.647 33.02,3.598 ; U23.4 40.637,4.688 40.51,4.561 R19.2 38.687,4.335 37.149,4.335 36.413,3.598 33.02,3.598
NetJP2_1: JP2.1 JP4.2 R8.1 | length 11.7
  Top Layer w0.508: JP4.2 49.944,24.478 51.435,24.478 ; JP2.1@49.794,31.232 50.188,30.838 51.181,29.845 cw(c50.568,29.232) 51.435,29.232 51.435,24.478 ; R8.1 53.853,24.478 51.435,24.478
NetJP2_2: JP2.2 U5.1 | length 15.4
  Top Layer w0.508: JP2.2 59.436,33.782 ccw(c59.436,35.315) 60.52,34.231 U5.1
NetJP3_1: JP3.1 JP5.2 R10.1 | length 11.7
  Top Layer w0.508: JP5.2 51.904,6.604 ; JP3.1@49.788,12.95 51.752,10.986 ; 51.753,10.985 cw(c50.679,9.912) 52.197,9.912 52.197,9.779 ; 52.197,6.604 ccw(c52.86,6.604) 52.198,6.565 ccw(c52.86,6.604) 52.212,6.462 ccw(c52.86,6.604) 52.718,5.956 ccw(c52.86,6.604) 52.86,5.941 R10.1 ; 52.198,6.604 52.198,9.779
NetJP3_2: JP3.2 U6.1 | length 16.6
  Top Layer w0.508: JP3.2 56.243,15.494 ccw(c56.056,18.112) 57.912,16.256 U6.1
NetJP4_1: JP4.1 R18.2 U20.4 | length 4.8
  Top Layer w0.305: U20.4 45.146,27.162 46.946,27.162 46.99,27.206 47.093,27.103 49.709,27.103 JP4.1
NetJP4_3: JP4.3 U11.5 U19.2 U20.1 U21.1 U21.2 | length 57.3
  Top Layer w0.305: U19.2 27.097,9.469 27.097,10.272 27.095,10.272 27.095,10.306 27.127,10.435 27.244,10.552 27.249,10.555 27.373,10.584 48.009,10.584 ccw(c48.009,11.087) 48.513,11.087 48.513,22.073 ; U11.5@39.998,26.41 41.262,26.41 ; 41.267,29.082 41.267,31.877 ; U20.1 42.444,29.082 41.262,29.082 41.262,26.41 ; U21.2 41.275,31.877 41.275,32.512 cw(c41.529,32.512) 41.529,32.766 42.418,32.766 42.469,32.817 U21.1 ; 48.513,24.257 48.513,22.073 ; 48.514,24.257 ccw(c47.897,24.257) 48.513,24.296 ccw(c47.897,24.257) 47.897,24.874 41.72,24.874 cw(c41.72,25.332) 41.262,25.332 41.262,26.41 ; JP4.3@49.53,21.971 49.428,22.073 48.513,22.073 ; JP4.3@49.73,22.044 JP4.3
NetJP5_1: JP5.1 U11.3 U16.1 U22.1 U23.1 U23.2 | length 52.4
  Top Layer w0.305: U16.1 23.622,23.393 23.622,24.384 cw(c24.003,24.384) 24.003,24.765 25.549,24.765 ccw(c25.549,25.578) 26.123,25.003 27.823,26.702 ; 27.824,26.701 cw(c28.668,25.857) 28.668,27.051 33.274,27.051 ; U11.3 33.274,27.051 ; 37.18,20.732 34.798,23.114 ccw(c34.349,22.665) 34.349,23.3 33.58,23.3 cw(c33.58,23.606) 33.274,23.606 33.274,27.051 ; 37.18,20.732 cw(c36.649,20.199) 37.401,20.185 ccw(c37.706,20.181) 37.401,20.182 ; 37.401,16.27 37.401,20.181 ; 37.406,16.176 ccw(c38.552,16.176) 37.406,16.138 ccw(c38.552,16.176) 37.493,15.737 ccw(c38.552,16.176) 37.741,15.366 37.853,15.255 cw(c36.949,14.351) 38.227,14.351 v1(38.227,12.598) ; v1(38.205,9.79) 38.215,9.779 48.663,9.779 cw(c48.663,8.912) JP5.1@49.276,9.525 ; U23.2@41.568,7.55 41.568,9.727 ; 42.517,9.627 U23.1 42.517,7.199 42.644,7.072 44.299,7.072 U22.1
  Bottom Layer w0.305: v1(38.205,9.79) 38.216,9.801 38.216,12.587 v1(38.227,12.598)
NetJP5_3: JP5.3 R20.2 U22.4 | length 8
  Top Layer w0.305: U22.4 47.102,4.98 47.471,4.98 48.207,4.244 ccw(c48.641,4.677) 48.641,4.064 JP5.3 53.263,4.064 cw(c53.263,3.531) 53.626,3.922 cw(c53.263,3.531) 53.64,3.908 54.23,3.318 R20.2
NetJP6_1: JP6.1 U9.2 U10.4 U12.1 | length 20.8
  Top Layer w0.305: U9.2 25.527,32.385 ccw(c26.14,32.385) 25.707,31.951 25.911,31.747 ccw(c26.543,32.378) 26.543,31.485 32.639,31.485 ; v1(32.004,26.162) 32.034,26.162 32.538,25.659 ; U12.1@32.04,22.058 32.04,22.869 cw(c32.521,22.869) 32.151,23.177 cw(c32.521,22.869) 32.181,23.209 ; 32.182,23.208 32.575,23.601 ; U10.4 32.512,33.032 32.639,32.905 32.639,31.485 ; 32.538,25.658 cw(c32.051,25.172) 32.737,25.223 cw(c32.051,25.172) 32.739,25.172 ; 32.572,23.604 ccw(c32.174,24.002) 32.737,24.002 32.737,25.172 ; JP6.1 32.639,30.099 32.639,31.485
  Bottom Layer w0.305: v1(32.004,26.162) 32.051,26.162 32.893,27.004 JP6.1
NetJP6_2: JP6.2 U11.7 | length 10.9
  Top Layer w0.305: JP6.2 31.496,28.702 ccw(c32.109,29.315) 32.109,28.448 34.185,28.448 ccw(c34.185,29.315) 34.797,28.701 34.925,28.829 cw(c35.479,28.275) 35.433,29.057 cw(c35.479,28.275) 35.479,29.058 35.712,29.058 ; 35.712,29.057 37.168,29.057 cw(c37.168,28.278) 37.719,28.829 38.759,27.789 ccw(c39.058,28.089) 38.977,27.673 ccw(c39.058,28.089) 39.058,27.665 ; 39.058,27.673 39.961,27.673 U11.7
NetJP7_1: JP7.1 U10.2 U12.4 U13.2 | length 24.6
  Top Layer w0.305: U10.2 30.247,33.934 34.223,33.934 cw(c34.223,33.641) 34.399,33.876 cw(c34.223,33.641) 34.459,33.816 cw(c34.223,33.641) 34.517,33.641 34.517,33.573 ; U12.4@33.902,24.776 33.918,24.792 33.918,25.686 v1(33.926,25.694) ; U12.4@33.954,24.683 U12.4 35.888,24.638 cw(c35.888,24.204) 36.195,24.511 JP7.1 37.191,23.622 39.623,21.191 39.711,21.102 cw(c39.312,20.701) 39.83,20.928 cw(c39.551,20.806) 39.856,20.808 39.856,19.152 cw(c39.551,19.152) 39.593,18.85 cw(c39.548,19.177) 39.548,18.847 U13.2 ; v1(34.519,29.72) 34.519,33.573
  Bottom Layer w0.305: v1@33.924,25.696 33.926,25.698 33.926,28.535 34.463,29.072 34.463,29.664 v1(34.519,29.72)
NetJP7_2: JP7.2 U11.6 | length 4.9
  Top Layer w0.305: 39.074,27.059 ccw(c39.074,26.728) 38.743,26.728 38.743,24.67 ccw(c39.148,24.67) 38.862,24.384 JP7.2 ; 39.074,27.059 39.981,27.059 U11.6
NetQ1_1: Q1.1 R8.2 R9.2 | length 3.7
  Top Layer w0.508: Q1.1@54.041,27.602 53.984,27.545 53.984,25.936 R8.2 R9.2
NetQ2_1: Q2.1 R10.2 R11.2 | length 3.7
  Top Layer w0.305: Q2.1 54.102,9.253 R10.2 R11.2
NetR3_1: R3.1 U3.1 | length 5.9
  Top Layer w0.508: R3.1 5.469,12.484 5.469,16.717 U3.1
NetR3_2: R3.2 R5.1 TP1.1 U2.4 VR2.2 VR2.3 | length 24.2
  Top Layer w0.508: R3.2@10.503,12.222 10.503,17.641 cw(c11.295,17.641) 11.295,18.433 13.868,18.433 13.909,18.474 U2.4 ; R3.2 10.515,11.855 11.211,11.159 R5.1@12.541,11.159 ; TP1.1@11.43,7.34 11.43,7.824 12.469,8.862 R5.1@12.469,11.018 ; R5.1@12.585,11.114 15.691,11.114 ; 15.691,9.746 15.691,11.114 ; 15.706,9.746 ccw(c16.156,9.746) 15.733,9.592 ccw(c16.156,9.746) 16.156,9.296 VR2.2 ; VR2.3 16.915,11.938 16.129,11.938 ccw(c16.129,11.5) 15.694,11.551 ccw(c16.129,11.5) 15.691,11.5 15.691,11.114
NetR4_2: R4.2 U2.1 | length 1.8
  Top Layer w0.508: U2.1 15.809,20.945 15.85,20.904 17.279,20.904 R4.2
NetR15_1: R15.1 U14.4 U15.1 U15.2 | length 8.5
  Top Layer w0.305: 18.919,34.581 18.919,34.643 cw(c19.201,34.643) 18.923,34.689 cw(c19.201,34.643) 19.201,34.925 U15.1 ; 18.923,33.13 18.923,33.985 U15.2 ; 18.923,34.016 18.923,34.581 ; 18.928,33.13 18.928,33.069 ccw(c19.651,33.069) 19.139,32.558 ; 19.14,32.558 19.844,31.854 19.847,31.854 20.193,31.508 R15.1@20.193,31.468 ; R15.1 20.399,31.262 20.399,30.074 20.526,29.947 U14.4
NetR16_1: R16.1 U17.4 U18.1 U18.2 | length 8.7
  Top Layer w0.381: R16.1@41.592,19.745 41.656,19.681 41.656,16.764 ; U18.2 43.059,16.764 41.656,16.764 ; U17.4 44.78,15.913 44.693,15.826 42.811,15.826 42.797,15.813 41.972,15.813 cw(c41.972,16.129) 41.656,16.129 41.656,16.764
NetU1_6: U1.6 U19.1 | length 10.9
  Top Layer w0.305: 24.765,12.182 ccw(c25.874,12.182) 25.18,11.317 25.191,11.306 ; 24.765,12.183 24.765,17.785 cw(c25.141,17.785) 25.141,18.161 U1.6 ; 25.192,11.305 25.997,10.5 cw(c25.703,10.205) 26.118,10.239 cw(c25.703,10.205) 26.12,10.205 ; 26.118,10.205 26.118,9.508 U19.1
NetU1_7: U1.7 U16.2 | length 5.8
  Top Layer w0.305: U16.2 24.511,19.812 ccw(c24.892,19.812) 24.892,19.431 U1.7
NetU14_2: U14.2 U16.4 | length 4.9
  Top Layer w0.381: U14.2@23.425,29 25.047,29 cw(c25.047,28.593) 25.451,28.65 cw(c25.047,28.593) 25.455,28.593 ; U16.4 25.451,26.06 25.451,28.593
NetU17_2: U17.2 U19.4 | length 25.7
  Top Layer w0.305: U19.4 27.991,12.011 27.991,11.735 28.364,11.361 ; 28.369,11.366 28.374,11.361 ccw(c28.704,11.691) 28.704,11.224 45.372,11.224 ccw(c45.372,11.572) 45.72,11.572 U17.2
VCC_9-36V: U7.1 U8.1 | length 22.6
  Top Layer w0.508: 4.373,29.79 U8.1 ; 4.377,29.794 cw(c5.133,30.549) 4.2,30.027 cw(c5.133,30.549) 4.135,30.165 cw(c5.133,30.549) 4.064,30.549 4.064,39.37 cw(c5.08,39.37) 5.08,40.386 13.172,40.386 U7.1
pads on no net: U2.3

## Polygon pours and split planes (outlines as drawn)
GND on Bottom Layer "GND_L02_P001" (solid, pour order 1): 70,1 1,1 1,49 70,49

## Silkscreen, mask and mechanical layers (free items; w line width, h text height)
Top Overlay:
  text "Лучшее из двух миров :: energy4all.ru" at 7.65,48.157 h2.03
  text "5V/ON" at 56.261,47.879 h1.27
  text "VDD +" at 53.594,44.704 h1.27 r90
  text "Мищук А.Л." at 52.705,42.418 h2.03
  text "УМ 07.10.22" at 52.705,40.513 h2.03
  text "High Lock" at 34.163,40.386 h1.4 r90
  text "High Delay" at 41.148,40.132 h1.4 r90
  text "+" at 22.098,38.1 h1.27
  text "CHARGE+" at 70.485,35.306 h1.27 r90
  text "GND" at 70.485,31.242 h1.27 r90
  text "Transistor ON" at 52.705,29.845 h1.4 r90
  text "Low-Voltage" at 13.081,28.448 h1.4 r90
  text "+ 9-36V" at 1.016,27.94 h1.27 r90
  text "Hi Lock ON" at 27.432,26.924 h1.4
  text "LV" at 13.081,25.4 h1.27 r90
  text "DRAIN" at 70.358,25.4 h1.27 r90
  text "Hi Delay ON" at 52.705,21.082 h1.4 r90
  text "LOAD +" at 70.358,20.828 h1.27 r90
  text "Low Lock OFF" at 35.663,20.764 h1.4
  text "+ V/CONTROL" at 1.143,16.383 h1.27 r90
  text "GND" at 70.358,15.621 h1.27 r90
  text "Transistor ON" at 52.705,11.557 h1.4 r90
  text "High Lock" at 30.988,10.033 h1.4
  text "DRAIN" at 70.358,9.779 h1.27 r90
  text "Low Delay" at 27.501,7.284 h1.4
  text "Ext-Divider" at 14.278,6.597 h1.4 r90
  text "High-Voltage" at 25.246,6.155 h1.4 r90
  text "Low Delay OFF" at 52.832,2.413 h1.4 r90
  text "HV" at 14.986,1.778 h1.27 r90
  text "GND" at 9.654,1.227 h1.27 r90
  text "Контроллер заряда АКБ/Конденсаторов." at 20.917,0.591 h2.03
Mechanical 2:
  the board outline again, w0.254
